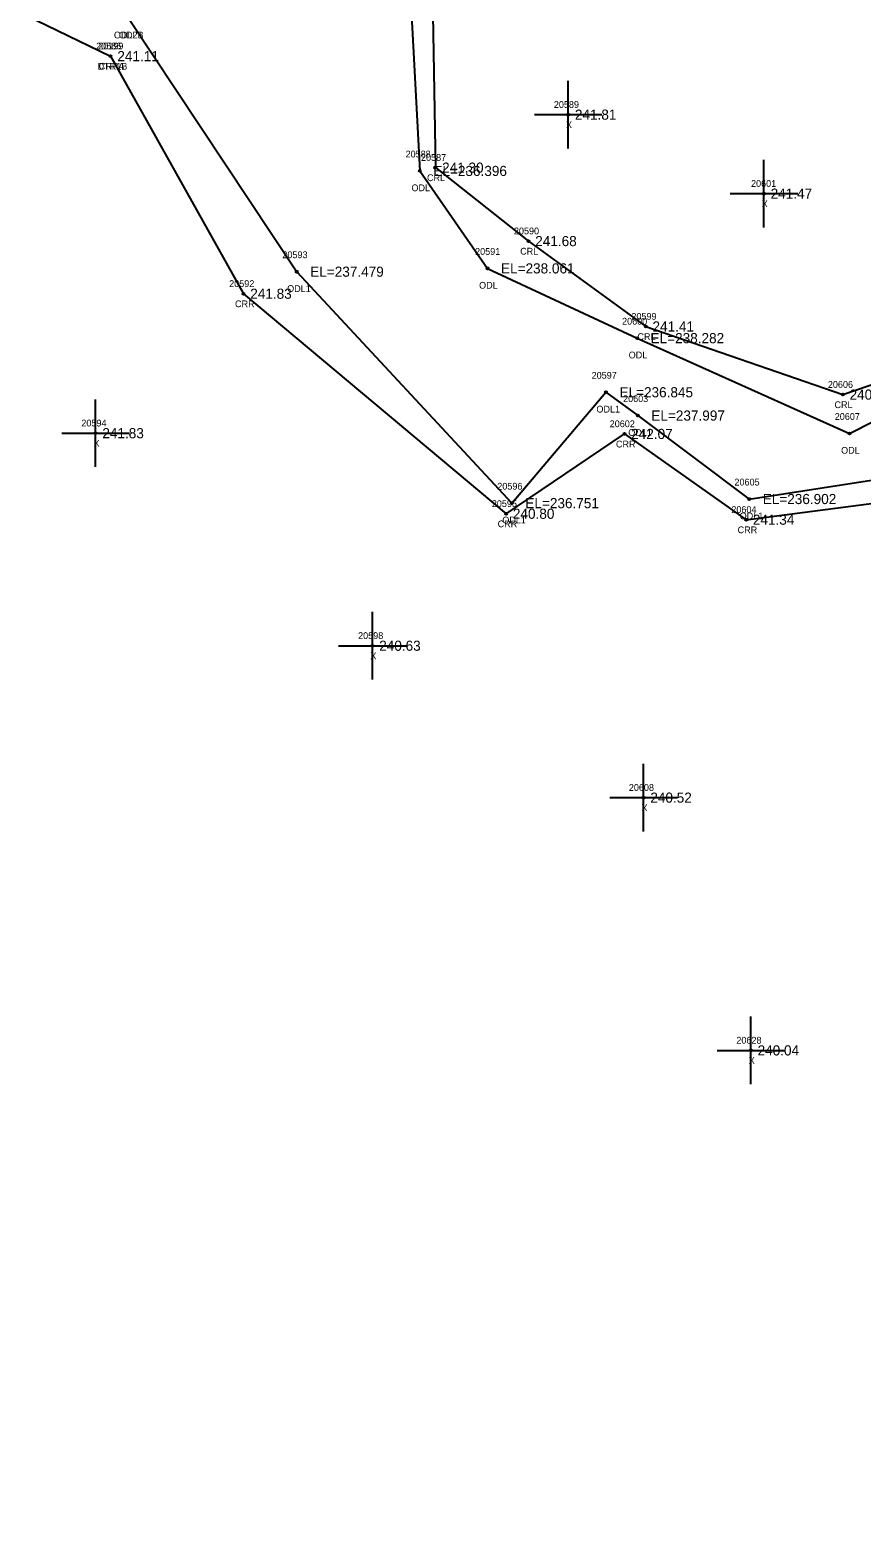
# Model space of a CAD drawing. Extents: x 2275563 to 2277161, y 1075719 to 1076412.
# Drawn here: x 2276319.5 to 2276442.5, y 1075736.8 to 1075959.9 of the extents above; entities that cross this region are included whole.
import ezdxf

# ---------------------------------------------------------------- set-up
doc = ezdxf.new("R2010")
doc.units = 0
for name, color, linetype in [('RD_EX_H2O', 7, 'Continuous'), ('RD_EX_H2O_txCode', 7, 'Continuous'), ('RD_EX_Misc', 7, 'Continuous'), ('RD_EX_Misc_txCode', 7, 'Continuous'), ('RD_EX_TX_H2O_ELEV', 7, 'Continuous'), ('RD_EX_TX_Misc_ELEV', 7, 'Continuous'), ('RD_SMD_Locator', 7, 'Continuous')]:
    doc.layers.add(name, color=color, linetype=linetype)

msp = doc.modelspace()

# ---------------------------------------------------------------- linework, layer by layer
at = {"layer": 'RD_EX_H2O'}
for points in [[(2276371.99, 1076084.86), (2276373.47, 1076057.63), (2276371.02, 1076053.34), (2276370.27, 1076037.47), (2276373.78, 1076001.78), (2276377.12, 1075939.07), (2276387.12, 1075924.65), (2276409.24, 1075914.33), (2276440.66, 1075900.23), (2276458.72, 1075909.41), (2276468.75, 1075909.62), (2276481.14, 1075898.88), (2276470.97, 1075847.84), (2276468.69, 1075801.1), (2276495.71, 1075755.91), (2276526.48, 1075747.54)], [(2276337.52, 1076082.32), (2276336.19, 1076056.07), (2276339.64, 1076049.32), (2276347.49, 1076019.86), (2276346.94, 1075980.53), (2276334.04, 1075961.68), (2276358.91, 1075924.16), (2276390.72, 1075889.91), (2276404.64, 1075906.32), (2276409.35, 1075902.87), (2276425.82, 1075890.52), (2276463.29, 1075896.33), (2276470.94, 1075887.1), (2276454.43, 1075853.34), (2276454.95, 1075812.59), (2276477.48, 1075753.76), (2276516.05, 1075739.78)], [(2276374.66, 1076053.77), (2276373.09, 1076038.49), (2276378.35, 1076001.85), (2276379.41, 1075939.56), (2276393.18, 1075928.69), (2276410.52, 1075916.05), (2276439.66, 1075905.97), (2276458.4, 1075912.38), (2276470.74, 1075911.86), (2276484.27, 1075900.43), (2276472.97, 1075846.67), (2276473.8, 1075804.25), (2276499.15, 1075757.95), (2276529.69, 1075749.92)], [(2275587.87, 1075932.23), (2275632.3, 1075945.74), (2275680.34, 1075962.3), (2275730.43, 1075971.98), (2275777.84, 1075981.49), (2275823.91, 1075987.34), (2275869.26, 1075992.75), (2275941.88, 1076000), (2275968.29, 1076005.71), (2275973.41, 1076009.09), (2276058.49, 1076013.63), (2276114.54, 1076018.47), (2276125.61, 1076012.99), (2276153.29, 1076014.06), (2276186.69, 1076017.67), (2276196.76, 1076016.05), (2276210.13, 1076008.45), (2276246.2, 1076005.42), (2276264.34, 1076010.6), (2276271.38, 1076006), (2276275.05, 1075983.37), (2276331.39, 1075956.06)], [(2276331.39, 1075956.06), (2276351.04, 1075920.9), (2276389.88, 1075888.34), (2276407.37, 1075900.15), (2276425.36, 1075887.46), (2276462.73, 1075892.32), (2276465.23, 1075885.12), (2276450.45, 1075853.62), (2276452.23, 1075813.27), (2276475.72, 1075752.81), (2276512.04, 1075736.79)]]:
    msp.add_lwpolyline(points, dxfattribs=at)
at = {"layer": 'RD_EX_Misc'}
for p, q in [((2276399.05, 1075942.4), (2276399.05, 1075952.4)), ((2276394.05, 1075947.4), (2276404.05, 1075947.4)), ((2276427.99, 1075930.71), (2276427.99, 1075940.71)), ((2276422.99, 1075935.71), (2276432.99, 1075935.71)), ((2276329.17, 1075895.26), (2276329.17, 1075905.26)), ((2276324.17, 1075900.26), (2276334.17, 1075900.26)), ((2276370.11, 1075863.81), (2276370.11, 1075873.81)), ((2276365.11, 1075868.81), (2276375.11, 1075868.81)), ((2276410.2, 1075841.33), (2276410.2, 1075851.33)), ((2276405.2, 1075846.33), (2276415.2, 1075846.33)), ((2276426.06, 1075803.93), (2276426.06, 1075813.93)), ((2276421.06, 1075808.93), (2276431.06, 1075808.93))]:
    msp.add_line(p, q, dxfattribs=at)
at = {"layer": 'RD_SMD_Locator'}
for centre in [(2276331.39, 1075956.06), (2276331.39, 1075956.06), (2276399.05, 1075947.4), (2276377.12, 1075939.07), (2276379.41, 1075939.56), (2276427.99, 1075935.71), (2276393.18, 1075928.69), (2276358.91, 1075924.16), (2276387.12, 1075924.65), (2276351.04, 1075920.9), (2276410.52, 1075916.05), (2276409.24, 1075914.33), (2276404.64, 1075906.32), (2276439.66, 1075905.97), (2276409.35, 1075902.87), (2276329.17, 1075900.26), (2276407.37, 1075900.15), (2276440.66, 1075900.23), (2276390.72, 1075889.91), (2276425.82, 1075890.52), (2276389.88, 1075888.34), (2276425.36, 1075887.46), (2276370.11, 1075868.81), (2276410.2, 1075846.33), (2276426.06, 1075808.93)]:
    msp.add_circle(centre, 0.15, dxfattribs=at)

# ---------------------------------------------------------------- texts
at = {"layer": 'RD_EX_H2O_txCode'}
for s, p in [('ODL2B', (2276331.88, 1075958.68)), ('ODL1', (2276332.63, 1075958.68)), ('20586', (2276329.25, 1075957.06)), ('20199', (2276329.56, 1075957.06)), ('DTR1B', (2276329.48, 1075954.06)), ('CRRA', (2276329.65, 1075954.06)), ('20588', (2276375.01, 1075941.07)), ('20587', (2276377.29, 1075940.56)), ('CRL', (2276378.18, 1075937.56)), ('ODL', (2276375.88, 1075936.07)), ('20590', (2276391.03, 1075929.69)), ('20591', (2276385.29, 1075926.65)), ('CRL', (2276391.95, 1075926.69)), ('20593', (2276356.79, 1075926.16)), ('20592', (2276348.92, 1075921.9)), ('ODL1', (2276357.5, 1075921.16)), ('ODL', (2276385.88, 1075921.65)), ('CRR', (2276349.79, 1075918.9)), ('20600', (2276407.02, 1075916.33)), ('20599', (2276408.4, 1075917.05)), ('CRL', (2276409.29, 1075914.05)), ('ODL', (2276408, 1075911.33)), ('20597', (2276402.52, 1075908.32)), ('20606', (2276437.45, 1075906.97)), ('20603', (2276407.17, 1075904.87)), ('CRL', (2276438.43, 1075903.97)), ('ODL1', (2276403.23, 1075903.32)), ('20607', (2276438.47, 1075902.23)), ('20602', (2276405.19, 1075901.15)), ('ODL1', (2276407.94, 1075899.87)), ('CRR', (2276406.12, 1075898.15)), ('ODL', (2276439.41, 1075897.23)), ('20596', (2276388.57, 1075891.91)), ('20605', (2276423.64, 1075892.52)), ('20595', (2276387.76, 1075889.34)), ('20604', (2276423.18, 1075888.46)), ('CRR', (2276388.62, 1075886.34)), ('ODL1', (2276389.31, 1075886.91)), ('ODL1', (2276424.41, 1075887.52)), ('CRR', (2276424.11, 1075885.46))]:
    msp.add_text(s, height=1, dxfattribs=at).set_placement(p)
at = {"layer": 'RD_EX_Misc_txCode'}
for s, p in [('20589', (2276396.93, 1075948.4)), ('X', (2276398.73, 1075945.4)), ('20601', (2276426.09, 1075936.71)), ('X', (2276427.67, 1075933.71)), ('20594', (2276327.06, 1075901.26)), ('X', (2276328.86, 1075898.26)), ('20598', (2276367.99, 1075869.81)), ('X', (2276369.8, 1075866.81)), ('20608', (2276408.02, 1075847.33)), ('X', (2276409.89, 1075844.33)), ('20628', (2276423.92, 1075809.93)), ('X', (2276425.75, 1075806.93))]:
    msp.add_text(s, height=1, dxfattribs=at).set_placement(p)
at = {"layer": 'RD_EX_TX_H2O_ELEV'}
for s, p in [('241.11', (2276332.39, 1075955.31)), ('241.11', (2276332.39, 1075955.31)), ('EL=236.396', (2276379.12, 1075938.32)), ('241.30', (2276380.41, 1075938.81)), ('241.68', (2276394.18, 1075927.94)), ('EL=238.061', (2276389.12, 1075923.9)), ('EL=237.479', (2276360.91, 1075923.41)), ('241.83', (2276352.04, 1075920.15)), ('241.41', (2276411.52, 1075915.3)), ('EL=238.282', (2276411.24, 1075913.58)), ('EL=236.845', (2276406.64, 1075905.57)), ('240.56', (2276440.66, 1075905.22)), ('EL=237.997', (2276411.35, 1075902.12)), ('242.07', (2276408.37, 1075899.4)), ('EL=236.751', (2276392.72, 1075889.16)), ('EL=236.902', (2276427.82, 1075889.77)), ('240.80', (2276390.88, 1075887.59)), ('241.34', (2276426.36, 1075886.71))]:
    msp.add_text(s, height=1.5, dxfattribs=at).set_placement(p)
at = {"layer": 'RD_EX_TX_Misc_ELEV'}
for s, p in [('241.81', (2276400.05, 1075946.65)), ('241.47', (2276428.99, 1075934.96)), ('241.83', (2276330.17, 1075899.51)), ('240.63', (2276371.11, 1075868.06)), ('240.52', (2276411.2, 1075845.58)), ('240.04', (2276427.06, 1075808.18))]:
    msp.add_text(s, height=1.5, dxfattribs=at).set_placement(p)

doc.saveas('drawing.dxf')
